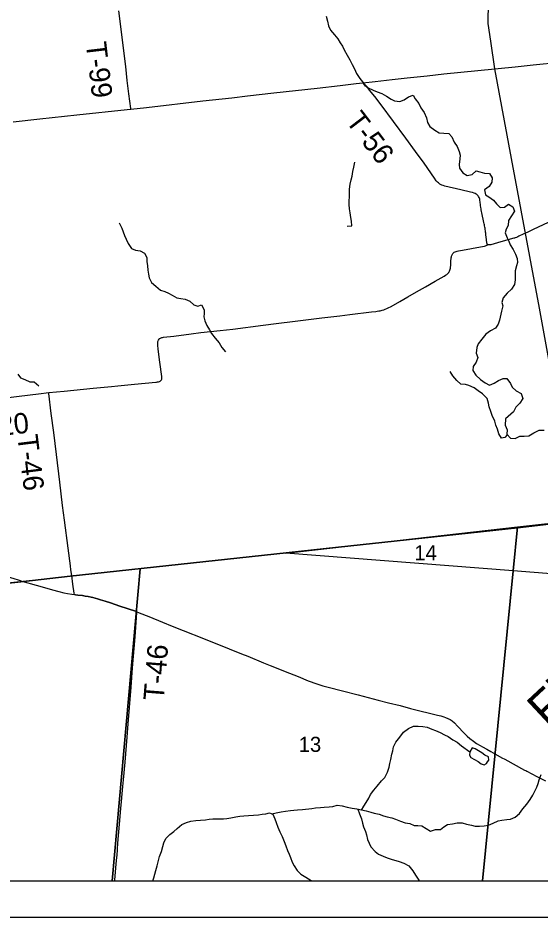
# Model space of a CAD drawing. Extents: x 0 to 34, y -5.4 to 22.
# Drawn here: x 4.732 to 6.179, y 14 to 16.492 of the extents above; entities that cross this region are included whole.
import ezdxf

# ---------------------------------------------------------------- set-up
doc = ezdxf.new("R2010")
doc.units = 0
for name, color, linetype in [('Default', 7, 'Continuous'), ('GM_X_County_Road', 7, 'Continuous'), ('GM_X_Minor_Lake', 7, 'Continuous'), ('GM_X_Minor_River', 7, 'Continuous'), ('GM_X_Minor_River_Text', 7, 'Continuous'), ('GM_X_Rail_Line', 7, 'Continuous'), ('GM_X_Section', 7, 'Continuous'), ('GM_X_Section_Text', 7, 'Continuous'), ('GM_X_Township_Road', 7, 'Continuous'), ('GM_X_Township_Road_Text', 7, 'Continuous'), ('SH_Data', 7, 'Continuous')]:
    doc.layers.add(name, color=color, linetype=linetype)

msp = doc.modelspace()

# ---------------------------------------------------------------- linework, layer by layer
at = {"layer": 'Default'}
for points in [[(4.9934, 14.1), (6.0193, 14.1), (6.1044, 14.9597), (5.4745, 15.009), (5.1643, 14.9757), (5.0709, 14.9656)], [(4.3725, 14.1), (4.9934, 14.1), (5.0709, 14.9656), (4.0448, 14.8547), (3.9754, 14.1403), (3.9753, 14.1377)], [(6.0193, 14.1), (7.0382, 14.1), (7.1062, 14.8804), (6.1044, 14.9597)]]:
    msp.add_lwpolyline(points, close=True, dxfattribs=at)
at = {"layer": 'GM_X_County_Road'}
for points in [[(4.7185, 16.204), (4.7926, 16.2124), (4.8952, 16.2234), (5.0348, 16.2385), (5.0448, 16.2396), (5.088, 16.2444), (5.2441, 16.2625), (5.3244, 16.2711), (5.3683, 16.2761), (5.4411, 16.2844), (5.561, 16.2977), (5.6252, 16.3051), (5.6696, 16.3102), (5.688, 16.3123), (5.7221, 16.3161), (5.769, 16.3213), (5.8104, 16.3259), (5.8666, 16.332), (5.9123, 16.337), (6.0063, 16.3464), (6.1102, 16.3568), (6.1602, 16.3621), (6.2351, 16.3696)], [(4.1389, 15.0666), (4.1408, 15.0665), (4.2163, 15.0618), (4.2796, 15.0583), (4.2872, 15.0578), (4.2953, 15.057), (4.3007, 15.0563), (4.3111, 15.0546), (4.3164, 15.0536), (4.3278, 15.0509), (4.3494, 15.0449), (4.4019, 15.0297), (4.4532, 15.015), (4.4818, 15.0065), (4.5533, 14.9862), (4.6276, 14.9647), (4.6623, 14.9545), (4.6939, 14.9458), (4.718, 14.9389), (4.7356, 14.9337), (4.7431, 14.9314)], [(4.7431, 14.9314), (4.7822, 14.9197), (4.8184, 14.9093), (4.8279, 14.9067), (4.8456, 14.9023), (4.8588, 14.8991), (4.8691, 14.897), (4.8809, 14.8949), (4.8883, 14.8938)], [(4.8883, 14.8938), (4.8918, 14.8933), (4.8983, 14.8924), (4.9111, 14.8908), (4.9186, 14.8896), (4.9261, 14.8883), (4.9347, 14.8867), (4.9397, 14.8856), (4.9528, 14.882), (4.9612, 14.8795), (4.9741, 14.8757), (4.9889, 14.8708), (5.0014, 14.8667), (5.0148, 14.8621), (5.0576, 14.8474), (5.0615, 14.8461)], [(5.0615, 14.8461), (5.0659, 14.8444), (5.0682, 14.8435), (5.0949, 14.8331), (5.1329, 14.8176), (5.1591, 14.8067), (5.1902, 14.7944), (5.2463, 14.7717), (5.317, 14.7436), (5.3513, 14.7299), (5.3691, 14.7228), (5.4129, 14.7049), (5.4312, 14.6974), (5.4844, 14.676), (5.5083, 14.6663), (5.5368, 14.6546), (5.56, 14.6465), (5.5766, 14.6413), (5.5916, 14.6371), (5.632, 14.627), (5.6753, 14.6159), (5.7306, 14.6015), (5.7588, 14.5941), (5.7914, 14.5859), (5.8202, 14.5784), (5.8462, 14.5719), (5.8725, 14.5653), (5.8948, 14.5597), (5.904, 14.5573), (5.9124, 14.5549), (5.9175, 14.5533), (5.9237, 14.5505), (5.9296, 14.5473), (5.9351, 14.5434), (5.9417, 14.5379), (5.9501, 14.5293), (5.9688, 14.5097), (5.9772, 14.5013), (5.9844, 14.4953), (5.9948, 14.4871), (6.0033, 14.4812), (6.0128, 14.4754), (6.0195, 14.4716), (6.0316, 14.4649), (6.0427, 14.4588), (6.0493, 14.4553), (6.0732, 14.4417), (6.0817, 14.4372), (6.1365, 14.4073), (6.1395, 14.4058), (6.1422, 14.4044), (6.1707, 14.3893), (6.194, 14.3771)]]:
    msp.add_lwpolyline(points, dxfattribs=at)
at = {"layer": 'GM_X_Minor_Lake'}
for points in [[(5.9849, 14.4576), (5.9833, 14.4482), (5.987, 14.4421), (5.9971, 14.4362), (6.0072, 14.4307), (6.0162, 14.4249), (6.0242, 14.4218), (6.0303, 14.4258), (6.0337, 14.4303)], [(6.0337, 14.4303), (6.0369, 14.4345), (6.0362, 14.4436), (6.0265, 14.449), (6.0178, 14.4552), (6.0081, 14.4607), (5.9995, 14.4665), (5.9908, 14.4693), (5.9849, 14.4576)]]:
    msp.add_lwpolyline(points, dxfattribs=at)
at = {"layer": 'GM_X_Minor_River'}
for points in [[(5.5864, 16.4968), (5.5904, 16.4835), (5.5932, 16.4705), (5.5983, 16.4587), (5.6094, 16.4456), (5.6187, 16.434), (5.6253, 16.4237), (5.6312, 16.4141), (5.6364, 16.4041), (5.6448, 16.3896), (5.6518, 16.3765), (5.6588, 16.3631), (5.6646, 16.3513), (5.6705, 16.3383), (5.6793, 16.3248), (5.6908, 16.311), (5.7028, 16.299), (5.7163, 16.2923), (5.7275, 16.2876), (5.7403, 16.2828), (5.7538, 16.2758), (5.7662, 16.2668), (5.7759, 16.2621), (5.7903, 16.2607), (5.8025, 16.2651), (5.8147, 16.2736), (5.8277, 16.2787), (5.8332, 16.2684), (5.8432, 16.2549), (5.8483, 16.2435), (5.8575, 16.2304), (5.8641, 16.2155), (5.8673, 16.2025), (5.8739, 16.1914), (5.8874, 16.1809), (5.8994, 16.1735), (5.9126, 16.1726), (5.9262, 16.1719)], [(5.9262, 16.1719), (5.9344, 16.1623), (5.9409, 16.1478), (5.9491, 16.1355), (5.9549, 16.1218), (5.9578, 16.1122), (5.9564, 16.1016), (5.9554, 16.0865), (5.9557, 16.0762), (5.9649, 16.0632), (5.9773, 16.0557), (5.9909, 16.0582), (6.0024, 16.0686), (6.0122, 16.0658), (6.025, 16.0618), (6.0387, 16.0615), (6.0464, 16.0493), (6.0451, 16.0375), (6.0377, 16.0247), (6.025, 16.0159), (6.0275, 16.0022), (6.0376, 15.9963), (6.0499, 15.987), (6.0585, 15.9773), (6.0689, 15.9669), (6.0806, 15.9675), (6.0921, 15.976), (6.1037, 15.9686), (6.1081, 15.9564), (6.0999, 15.944), (6.0914, 15.9305), (6.0904, 15.9172), (6.0857, 15.9067), (6.0829, 15.8965), (6.0879, 15.8831), (6.0927, 15.8736), (6.0959, 15.8637), (6.1044, 15.8506), (6.111, 15.8376), (6.1154, 15.8258), (6.1163, 15.8147), (6.1139, 15.8049), (6.1106, 15.7917), (6.11, 15.7792), (6.1098, 15.7663), (6.1081, 15.7534), (6.1003, 15.7407), (6.088, 15.7295), (6.0765, 15.7164), (6.0736, 15.7039), (6.0757, 15.6944), (6.0724, 15.6797), (6.0667, 15.6547), (6.0631, 15.6438), (6.0558, 15.6321), (6.0416, 15.6252), (6.0286, 15.6155), (6.0174, 15.6021), (6.0077, 15.5893), (6.0042, 15.5784), (6.0024, 15.5629), (6.0063, 15.5506), (6.002, 15.5378), (5.9942, 15.5258), (5.9929, 15.5152), (6.001, 15.5018), (6.0137, 15.4902), (6.0267, 15.4805), (6.0387, 15.4739), (6.0517, 15.4797), (6.0643, 15.4875), (6.0765, 15.4926), (6.0867, 15.4928), (6.0975, 15.4786), (6.1015, 15.469), (6.1127, 15.4586), (6.1265, 15.4511), (6.1316, 15.4378), (6.1231, 15.4243), (6.1123, 15.4134), (6.106, 15.4007), (6.083, 15.3806), (6.0823, 15.3635), (6.0878, 15.3505), (6.0872, 15.3384), (6.0976, 15.3272), (6.1105, 15.3262), (6.123, 15.3325), (6.1352, 15.333), (6.1484, 15.3343), (6.1622, 15.3424), (6.1763, 15.3498), (6.1907, 15.3499)], [(5.6446, 15.9152), (5.6575, 15.9162), (5.6569, 15.9287), (5.6548, 15.939), (5.6528, 15.9519), (5.6511, 15.9629), (5.6501, 15.9751), (5.6499, 15.9846), (5.6509, 15.9978), (5.6514, 16.0073), (5.6512, 16.0179), (5.6526, 16.0312), (5.6558, 16.0433), (5.6582, 16.0539), (5.6603, 16.0664), (5.6632, 16.0788), (5.6657, 16.0921)], [(5.0128, 15.9247), (5.0201, 15.9097), (5.0238, 15.8998), (5.0274, 15.8891), (5.0317, 15.8792), (5.0376, 15.867), (5.0468, 15.8535), (5.0581, 15.8484), (5.0706, 15.8463), (5.0829, 15.8404), (5.0892, 15.8278), (5.0894, 15.8171), (5.0911, 15.8053), (5.0924, 15.7928), (5.0941, 15.7818), (5.0958, 15.7715), (5.102, 15.7589), (5.1144, 15.7492), (5.1267, 15.738), (5.1387, 15.7336), (5.1488, 15.7293), (5.159, 15.7238), (5.1725, 15.7167), (5.183, 15.7143), (5.1955, 15.7125), (5.2086, 15.707), (5.2191, 15.697), (5.2307, 15.693), (5.2406, 15.6966), (5.2483, 15.6832), (5.2478, 15.6733), (5.2476, 15.6635), (5.2497, 15.6524), (5.2552, 15.6398), (5.2633, 15.6276), (5.2684, 15.6176), (5.2784, 15.6042), (5.2896, 15.5915), (5.2969, 15.5784), (5.3077, 15.5672)], [(4.7319, 15.5048), (4.7393, 15.4948), (4.7513, 15.4897), (4.7649, 15.4838), (4.7773, 15.4836), (4.79, 15.4727)], [(6.0883, 15.3371), (6.0818, 15.3297), (6.0719, 15.3273), (6.0649, 15.3391), (6.0609, 15.3521), (6.0562, 15.3639), (6.0541, 15.3746), (6.0468, 15.3906), (6.0424, 15.401), (6.0377, 15.4139), (6.0364, 15.4242), (6.0325, 15.4375), (6.0198, 15.4499), (6.0075, 15.4588), (5.997, 15.467), (5.982, 15.4737), (5.9722, 15.4761), (5.9593, 15.4767), (5.9485, 15.4875), (5.9378, 15.5002), (5.9304, 15.5125)], [(5.6846, 14.2966), (5.6904, 14.3076), (5.6974, 14.3177), (5.7044, 14.3294), (5.7095, 14.3399), (5.7188, 14.3519), (5.728, 14.3623), (5.74, 14.3773), (5.7485, 14.387), (5.7563, 14.4013), (5.7611, 14.4153), (5.7628, 14.4251), (5.7652, 14.4368), (5.7685, 14.4512), (5.7709, 14.461), (5.7734, 14.4716), (5.7793, 14.4848), (5.7901, 14.4982), (5.8009, 14.5121), (5.8147, 14.5229), (5.8281, 14.5287), (5.8409, 14.5289), (5.8538, 14.5283), (5.8662, 14.5258), (5.8794, 14.5207), (5.8892, 14.5171), (5.9027, 14.5112), (5.9143, 14.5053), (5.9241, 14.5002), (5.9375, 14.4912), (5.9495, 14.4846), (5.9615, 14.4749), (5.9849, 14.4576)], [(5.4356, 14.2862), (5.4479, 14.2892), (5.4612, 14.2913), (5.4737, 14.293), (5.487, 14.2954), (5.4965, 14.2964), (5.5067, 14.297), (5.5203, 14.2979), (5.5469, 14.3005), (5.5571, 14.3026), (5.5708, 14.3039), (5.5806, 14.3045), (5.5946, 14.3054), (5.6045, 14.3067), (5.6166, 14.3096), (5.6302, 14.3082), (5.6442, 14.3042), (5.6581, 14.3021), (5.6714, 14.2999), (5.6842, 14.2967), (5.697, 14.2942), (5.7098, 14.291), (5.7196, 14.2878), (5.7328, 14.2849), (5.7456, 14.2809), (5.7557, 14.2781), (5.7682, 14.2748), (5.7783, 14.2712), (5.7922, 14.2657), (5.8054, 14.2613), (5.8186, 14.2592), (5.8299, 14.2537), (5.8401, 14.2539), (5.8518, 14.253), (5.8634, 14.2452), (5.8758, 14.2382), (5.8891, 14.2429), (5.9031, 14.243), (5.9127, 14.2504), (5.9226, 14.256), (5.9367, 14.2584), (5.9496, 14.2612), (5.9636, 14.2606), (5.9752, 14.2574), (5.9892, 14.2545), (5.9994, 14.252), (6.0115, 14.2515), (6.0243, 14.2528), (6.0365, 14.2548), (6.0494, 14.2599), (6.0632, 14.2665), (6.073, 14.2686), (6.0874, 14.2699), (6.0977, 14.2713), (6.1099, 14.2768), (6.1222, 14.2868), (6.1318, 14.2999), (6.1427, 14.3126), (6.152, 14.3257), (6.1593, 14.3381), (6.1652, 14.3506), (6.1699, 14.3603), (6.1739, 14.3705), (6.1767, 14.3803), (6.1823, 14.3954)], [(5.106, 14.1), (5.1089, 14.109), (5.111, 14.1188), (5.1138, 14.1286), (5.1174, 14.1422), (5.1218, 14.1562), (5.1246, 14.1675), (5.1294, 14.1815), (5.1338, 14.1951), (5.1366, 14.2053), (5.1414, 14.2173), (5.1533, 14.2285), (5.1636, 14.2374), (5.1736, 14.2456), (5.1859, 14.256), (5.1989, 14.2623), (5.2114, 14.2658), (5.2247, 14.2675), (5.2383, 14.268), (5.252, 14.2693), (5.2622, 14.2711), (5.2717, 14.2724), (5.2861, 14.2718), (5.302, 14.2723), (5.3114, 14.2733), (5.3221, 14.275), (5.3357, 14.2774), (5.3467, 14.2795), (5.3577, 14.2805), (5.3714, 14.2818), (5.3846, 14.2827), (5.399, 14.2836), (5.4089, 14.2849), (5.4191, 14.2863), (5.429, 14.2884), (5.4388, 14.2852), (5.4439, 14.2718), (5.4479, 14.2623), (5.4526, 14.2493), (5.4576, 14.2363), (5.4642, 14.223), (5.47, 14.2092), (5.4748, 14.1974), (5.4791, 14.1848), (5.4838, 14.1745), (5.4871, 14.1645), (5.4918, 14.1519), (5.4977, 14.142), (5.5058, 14.129), (5.5162, 14.1185)], [(5.6744, 14.2992), (5.6787, 14.2858), (5.6838, 14.2724), (5.6873, 14.2599), (5.6902, 14.2503), (5.6949, 14.2373), (5.6981, 14.2274), (5.7013, 14.2149), (5.7053, 14.2046), (5.7104, 14.1942), (5.722, 14.1815), (5.7317, 14.1745), (5.7441, 14.1683), (5.7553, 14.1639), (5.7689, 14.1595), (5.779, 14.1563), (5.7888, 14.1535), (5.8016, 14.1491), (5.8151, 14.1421), (5.8266, 14.1278), (5.8336, 14.1164), (5.8432, 14.1022), (5.8457, 14.1)], [(5.5162, 14.1185), (5.5297, 14.11), (5.5447, 14.1014), (5.5463, 14.1)]]:
    msp.add_lwpolyline(points, dxfattribs=at)
at = {"layer": 'GM_X_Rail_Line'}
for points in [[(4.0439, 14.8538), (4.7395, 14.9295), (4.8765, 14.9444), (6.1164, 15.0793), (6.4403, 15.1171), (6.4463, 15.1177), (6.92, 15.1674), (6.9294, 15.1684), (6.9348, 15.169), (6.9914, 15.1749), (7.0389, 15.1799), (7.3134, 15.2082), (7.6796, 15.247), (7.6929, 15.2483), (7.8942, 15.2734), (7.8983, 15.2739), (8.1702, 15.3079), (8.1991, 15.5295), (8.9, 15.5944), (8.9, 19.2127)], [(6.1298, 17.0307), (6.0905, 16.9105), (6.0657, 16.8233), (6.0521, 16.7659), (6.0427, 16.7106), (6.0374, 16.6619), (6.0337, 16.61), (6.035, 16.5368), (6.0346, 16.4766), (6.0418, 16.428), (6.0526, 16.3516), (6.0987, 16.1024), (6.1764, 15.688), (6.2405, 15.3368), (6.3349, 14.8243), (6.4523, 14.2374), (6.4858, 14.1034), (6.4871, 14.1)]]:
    msp.add_lwpolyline(points, dxfattribs=at)
msp.add_lwpolyline([(2.9527, 14.1), (8.0559, 14.1), (8.0925, 14.4946), (8.0933, 14.5029), (8.1066, 14.6429), (8.1702, 15.3079), (7.8983, 15.2739), (7.8942, 15.2734), (7.6929, 15.2483), (7.6796, 15.247), (7.3134, 15.2082), (7.0389, 15.1799), (6.9914, 15.1749), (6.9348, 15.169), (6.9294, 15.1684), (6.92, 15.1674), (6.4463, 15.1177), (6.4403, 15.1171), (6.1164, 15.0793), (4.8765, 14.9444), (4.7395, 14.9295), (4.0439, 14.8538), (3.0059, 14.7462), (2.9641, 14.2324)], close=True, dxfattribs=at)
at = {"layer": 'GM_X_Section'}
for points in [[(7.1421, 15.1859), (7.1062, 14.8804), (6.1044, 14.9597), (6.1164, 15.0815), (6.4432, 15.1181), (6.9566, 15.1729)], [(6.1164, 15.0815), (6.1044, 14.9597), (5.4745, 15.009)]]:
    msp.add_lwpolyline(points, close=True, dxfattribs=at)
at = {"layer": 'GM_X_Township_Road'}
msp.add_line((4.8811, 14.9467), (4.8789, 14.9625), dxfattribs=at)
for points in [[(5.0448, 16.2396), (5.0446, 16.2411), (5.0393, 16.2822), (5.0351, 16.3186), (5.0306, 16.3581), (5.0117, 16.5123)], [(6.0346, 15.8637), (6.0337, 15.8641), (6.033, 15.8648), (6.0325, 15.8659), (6.0322, 15.8671), (6.032, 15.8682), (6.0308, 15.8778), (6.0293, 15.8911), (6.0288, 15.8957), (6.0284, 15.8988), (6.0279, 15.902), (6.0273, 15.9059), (6.0267, 15.9096), (6.0262, 15.9127), (6.0256, 15.9161), (6.025, 15.919), (6.0243, 15.9219), (6.0235, 15.9257), (6.0177, 15.9518), (6.0168, 15.9561), (6.0161, 15.9603), (6.0155, 15.9635), (6.015, 15.967), (6.0143, 15.9725), (6.0138, 15.9765), (6.0134, 15.9794), (6.013, 15.983), (6.0127, 15.9861), (6.0121, 15.9902), (6.0112, 15.9927), (6.0104, 15.9947), (6.0089, 15.9974), (6.0073, 15.9993), (6.0058, 16.001), (6.004, 16.0028), (6.0021, 16.0042), (5.9996, 16.0056), (5.9967, 16.0066), (5.9915, 16.0083), (5.986, 16.0097), (5.9595, 16.016), (5.9154, 16.0264), (5.9109, 16.0276), (5.9069, 16.0291), (5.9035, 16.0307), (5.9013, 16.0319), (5.8992, 16.0333), (5.8973, 16.0349), (5.8952, 16.0369), (5.8934, 16.0387), (5.8914, 16.041), (5.8862, 16.048), (5.8575, 16.0893), (5.8343, 16.1217), (5.8073, 16.1588), (5.7725, 16.2057), (5.7385, 16.2515), (5.7212, 16.2743), (5.7113, 16.2869), (5.7033, 16.2958), (5.6979, 16.301), (5.6953, 16.3036), (5.6926, 16.3067), (5.6903, 16.3095), (5.688, 16.3123)], [(6.3405, 15.9872), (6.3369, 15.9861), (6.3334, 15.9851), (6.3303, 15.984), (6.3174, 15.9786), (6.2849, 15.9637), (6.2322, 15.9394), (6.2013, 15.9249), (6.1605, 15.9061), (6.1452, 15.8989)], [(6.1452, 15.8989), (6.1327, 15.8929), (6.1206, 15.8873), (6.1177, 15.8859), (6.1135, 15.8841), (6.1106, 15.8829), (6.1085, 15.882), (6.1067, 15.8815), (6.0773, 15.8734), (6.0615, 15.8692), (6.0428, 15.8637), (6.0411, 15.8633), (6.0394, 15.8631), (6.0384, 15.8629), (6.0373, 15.863), (6.0361, 15.8632), (6.0346, 15.8637)], [(4.6819, 15.4375), (4.7356, 15.4439), (4.7892, 15.4506), (4.8172, 15.4536), (4.8597, 15.458), (4.9401, 15.4659), (4.9914, 15.4709), (5.0085, 15.4726), (5.0549, 15.4771), (5.1139, 15.4826), (5.1159, 15.4828), (5.1189, 15.4832), (5.1214, 15.4837), (5.1241, 15.4846), (5.1261, 15.4856), (5.1282, 15.487), (5.1294, 15.4888), (5.1303, 15.4909), (5.1309, 15.4929), (5.1312, 15.4957), (5.1312, 15.4985), (5.1255, 15.5378), (5.1207, 15.5742), (5.1195, 15.585), (5.1193, 15.5881), (5.1193, 15.5905), (5.1194, 15.5932), (5.1196, 15.5952), (5.1203, 15.5976), (5.1212, 15.5995), (5.123, 15.6018), (5.1246, 15.6036), (5.1267, 15.605), (5.1287, 15.606), (5.1306, 15.6066), (5.1323, 15.6069), (5.1358, 15.6074), (5.1643, 15.6103), (5.2122, 15.6166), (5.2391, 15.62), (5.2928, 15.6258), (5.328, 15.63), (5.4112, 15.6406), (5.4475, 15.6454), (5.4999, 15.6519), (5.5746, 15.6606), (5.6245, 15.6668), (5.6516, 15.6704), (5.7121, 15.6772), (5.7236, 15.6786), (5.7275, 15.6792), (5.7322, 15.68), (5.7364, 15.6808), (5.7412, 15.682), (5.7461, 15.6834), (5.7503, 15.6848), (5.7545, 15.6866), (5.7582, 15.6884), (5.7661, 15.6925), (5.7901, 15.7066), (5.8125, 15.7194), (5.8364, 15.7333), (5.8613, 15.7472), (5.8886, 15.763), (5.9137, 15.7769), (5.9175, 15.7792), (5.9205, 15.7813), (5.9229, 15.783), (5.9247, 15.7848), (5.9263, 15.7868), (5.9276, 15.789), (5.9284, 15.7905), (5.9293, 15.7927), (5.9302, 15.7955), (5.9306, 15.7983), (5.9315, 15.8089), (5.9322, 15.8215), (5.9324, 15.8235), (5.9325, 15.8251), (5.9328, 15.8276), (5.9334, 15.8303), (5.9339, 15.8324), (5.9344, 15.8338), (5.9352, 15.8355), (5.9363, 15.8374), (5.9378, 15.8394), (5.9395, 15.841), (5.9414, 15.8426), (5.9436, 15.844), (5.9463, 15.8451), (5.9492, 15.846), (5.9533, 15.8468), (5.964, 15.8487), (6.0142, 15.8575), (6.0251, 15.8601), (6.0276, 15.8608), (6.0297, 15.8615), (6.0331, 15.863), (6.0346, 15.8637)], [(4.8789, 14.9625), (4.8774, 14.9733), (4.8709, 15.0226), (4.861, 15.1003), (4.8558, 15.141), (4.8481, 15.2052), (4.8385, 15.2822), (4.831, 15.3433), (4.8244, 15.3957), (4.8175, 15.4512), (4.8172, 15.4536)], [(4.8883, 14.8938), (4.8878, 14.8974), (4.8845, 14.9229), (4.8811, 14.9467)], [(5.0615, 14.8461), (5.0576, 14.8474), (5.0148, 14.8621), (5.0014, 14.8667), (4.9889, 14.8708), (4.9741, 14.8757), (4.9612, 14.8795), (4.9528, 14.882), (4.9397, 14.8856), (4.9347, 14.8867), (4.9261, 14.8883), (4.9186, 14.8896), (4.9111, 14.8908), (4.8983, 14.8924), (4.8918, 14.8933), (4.8883, 14.8938)], [(5.0002, 14.1), (5.0004, 14.1017), (5.0044, 14.1475), (5.006, 14.1648), (5.0067, 14.1716), (5.007, 14.1753), (5.0075, 14.1821), (5.0077, 14.1882), (5.009, 14.2049), (5.0134, 14.2569), (5.0172, 14.3009), (5.0189, 14.3201), (5.0209, 14.3417), (5.0227, 14.3615), (5.0245, 14.3806), (5.0288, 14.4295), (5.0345, 14.4983), (5.0374, 14.5355), (5.0454, 14.637), (5.0497, 14.6909), (5.0564, 14.7764), (5.0606, 14.8306), (5.0613, 14.843), (5.0615, 14.8461)]]:
    msp.add_lwpolyline(points, dxfattribs=at)
at = {"layer": 'SH_Data'}
for p, q in [((2.1, 14.1), (8.9, 14.1)), ((2, 14), (9, 14))]:
    msp.add_line(p, q, dxfattribs=at)

# ---------------------------------------------------------------- texts
at = {"layer": 'GM_X_Minor_River_Text'}
msp.add_text('Flat', height=0.09471, rotation=43.0301, dxfattribs=at).set_placement((6.1994, 14.5233))
at = {"layer": 'GM_X_Section_Text'}
for s, p in [('14', (5.8306, 14.9889)), ('13', (5.5102, 14.4577))]:
    msp.add_text(s, height=0.04186, rotation=0, dxfattribs=at).set_placement(p)
at = {"layer": 'GM_X_Township_Road_Text'}
for s, rotation, p in [('T-99', 276.7309, (4.9198, 16.4228)), ('T-56', 307.4388, (5.6386, 16.206)), ('T-220', 6.9531, (4.5682, 15.319)), ('T-46', 277.0814, (4.7298, 15.3338)), ('T-46', 85.4133, (5.136, 14.5981))]:
    msp.add_text(s, height=0.05682, rotation=rotation, dxfattribs=at).set_placement(p)

doc.saveas('drawing.dxf')
